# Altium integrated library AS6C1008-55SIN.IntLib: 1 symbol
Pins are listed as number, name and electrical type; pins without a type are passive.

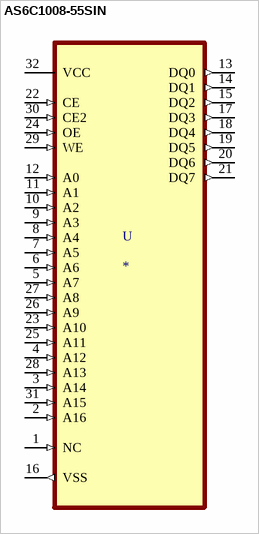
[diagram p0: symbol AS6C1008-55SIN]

## AS6C1008-55SIN
designator U
SRAM - Asynchronous Memory IC 1Mb _128K x 8_ Parallel 55ns 32-SOP; MP: AS6C1008-55SIN; MF: Alliance Memory,
footprint SOIC127P1407X299-32N
pins: 1 NC (in), 2 A16 (in), 3 A14 (in), 4 A12 (in), 5 A7 (in), 6 A6 (in), 7 A5 (in), 8 A4 (in), 9 A3 (in), 10 A2 (in), 11 A1 (in), 12 A0 (in), 13 DQ0 (out), 14 DQ1 (out), 15 DQ2 (out), 16 VSS (out), 17 DQ3 (out), 18 DQ4 (out), 19 DQ5 (out), 20 DQ6 (out), 21 DQ7 (out), 22 CE (in), 23 A10 (in), 24 OE (in), 25 A11 (in), 26 A9 (in), 27 A8 (in), 28 A13 (in), 29 WE (in), 30 CE2 (in), 31 A15 (in), 32 VCC (power)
